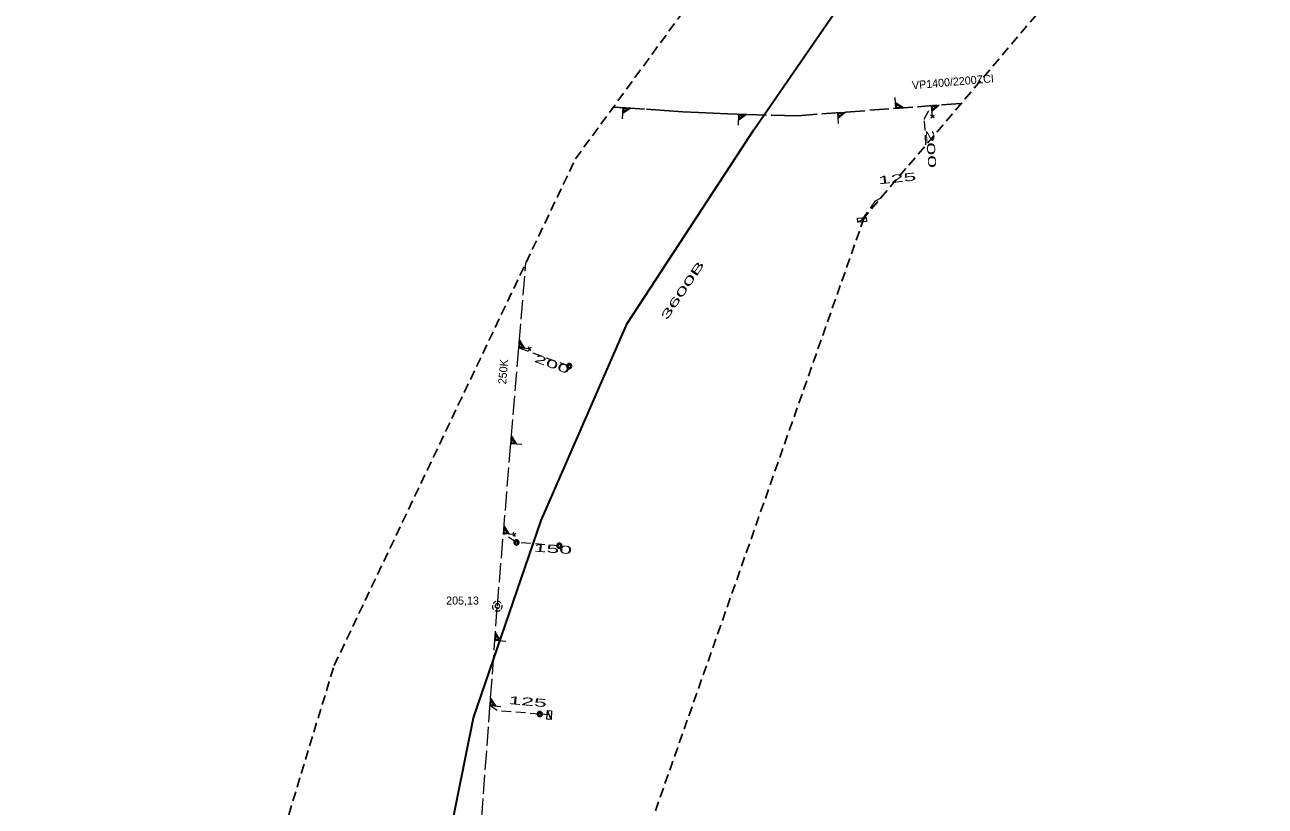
# Model space of a CAD drawing. Extents: x -744446 to -743929, y -1041261 to -1040599.
# Drawn here: x -744445.1 to -744321.1, y -1040836.2 to -1040758 of the extents above; entities that cross this region are included whole.
import ezdxf

# ---------------------------------------------------------------- set-up
doc = ezdxf.new("R2010")
doc.units = 0
doc.header["$LTSCALE"] = 0.32
doc.linetypes.add('LONG_DASHED', pattern=[7.5, 6, -1.5])
doc.linetypes.add('MEDIUM_DASHED', pattern=[4.5, 3, -1.5])
for name, color, linetype, lineweight in [('1', 7, 'MEDIUM_DASHED', 25), ('18', 7, 'Continuous', 13), ('20', 7, 'LONG_DASHED', 13), ('49', 7, 'MEDIUM_DASHED', 13)]:
    doc.layers.add(name, color=color, linetype=linetype, lineweight=lineweight)

msp = doc.modelspace()

# ---------------------------------------------------------------- linework, layer by layer
at = {"layer": '1'}
msp.add_lwpolyline([(-744438.077, -1041259.731), (-744438.679, -1041250.888), (-744445.125, -1041198.426), (-744434.434, -1041080.103), (-744426.87, -1040938.41), (-744425.446, -1040859.072), (-744414.192, -1040822.094), (-744390.076, -1040771.45), (-744357.118, -1040726.434), (-744307.278, -1040693.475), (-744241.36, -1040670.967), (-743937.498, -1040598.618), (-743928.655, -1040619.519), (-744129.684, -1040665.585), (-744218.109, -1040687.29), (-744311.358, -1040718.641), (-744361.198, -1040777.323), (-744391.745, -1040864.141), (-744411.355, -1041059.185), (-744416.379, -1041145.154), (-744432.569, -1041193.163), (-744432.047, -1041202.053), (-744422.803, -1041230.992), (-744424.813, -1041260.936)], close=True, dxfattribs=at)
at = {"layer": '18'}
for p, q in [((-744354.206, -1040767.325), (-744354.56, -1040767.082)), ((-744354.544, -1040767.339), (-744354.192, -1040767.067)), ((-744361.838, -1040777.771), (-744360.989, -1040777.31)), ((-744394.495, -1040790.289), (-744394.79, -1040790.601)), ((-744394.534, -1040790.625), (-744394.747, -1040790.235)), ((-744396.036, -1040808.866), (-744396.331, -1040809.178)), ((-744396.075, -1040809.202), (-744396.288, -1040808.812)), ((-744392.506, -1040827.502), (-744392.859, -1040826.603))]:
    msp.add_line(p, q, dxfattribs=at)
for points in [[(-744358.13, -1040765.299), (-744358.047, -1040766.392), (-744357.279, -1040766.334), (-744358.091, -1040765.815)], [(-744385.356, -1040767.426), (-744385.303, -1040766.331), (-744384.534, -1040766.368), (-744385.331, -1040766.908)], [(-744385.276, -1040766.793), (-744385.256, -1040766.377), (-744384.69, -1040766.404), (-744385.276, -1040766.794)], [(-744385.225, -1040766.711), (-744385.211, -1040766.421), (-744384.839, -1040766.438), (-744385.226, -1040766.711)], [(-744373.762, -1040768.081), (-744373.722, -1040766.986), (-744372.953, -1040767.014), (-744373.743, -1040767.564)], [(-744363.753, -1040767.919), (-744363.836, -1040766.826), (-744363.068, -1040766.768), (-744363.792, -1040767.402)], [(-744363.751, -1040767.281), (-744363.782, -1040766.866), (-744363.218, -1040766.824), (-744363.751, -1040767.282)], [(-744363.711, -1040767.194), (-744363.732, -1040766.903), (-744363.361, -1040766.875), (-744363.712, -1040767.194)], [(-744358.031, -1040765.929), (-744358, -1040766.344), (-744357.436, -1040766.301), (-744358.031, -1040765.928)], [(-744357.978, -1040766.009), (-744357.956, -1040766.3), (-744357.586, -1040766.272), (-744357.979, -1040766.009)], [(-744354.375, -1040767.209), (-744354.458, -1040766.117), (-744353.69, -1040766.059), (-744354.414, -1040766.693)], [(-744354.373, -1040766.571), (-744354.404, -1040766.157), (-744353.84, -1040766.114), (-744354.373, -1040766.573)], [(-744354.333, -1040766.484), (-744354.355, -1040766.193), (-744353.984, -1040766.165), (-744354.334, -1040766.484)], [(-744373.689, -1040767.448), (-744373.674, -1040767.032), (-744373.108, -1040767.052), (-744373.689, -1040767.449)], [(-744373.639, -1040767.365), (-744373.629, -1040767.074), (-744373.257, -1040767.088), (-744373.64, -1040767.365)], [(-744394.636, -1040790.438), (-744395.728, -1040790.347), (-744395.664, -1040789.58), (-744395.152, -1040790.395)], [(-744395.266, -1040790.336), (-744395.68, -1040790.301), (-744395.633, -1040789.737), (-744395.264, -1040790.336)], [(-744395.345, -1040790.282), (-744395.636, -1040790.258), (-744395.605, -1040789.887), (-744395.345, -1040790.283)], [(-744395.43, -1040800.022), (-744396.522, -1040799.931), (-744396.458, -1040799.164), (-744395.946, -1040799.979)], [(-744396.059, -1040799.92), (-744396.474, -1040799.885), (-744396.427, -1040799.321), (-744396.058, -1040799.92)], [(-744396.139, -1040799.866), (-744396.429, -1040799.842), (-744396.398, -1040799.471), (-744396.139, -1040799.867)], [(-744396.177, -1040809.015), (-744397.269, -1040808.924), (-744397.205, -1040808.157), (-744396.693, -1040808.972)], [(-744396.807, -1040808.913), (-744397.221, -1040808.878), (-744397.174, -1040808.314), (-744396.805, -1040808.913)], [(-744396.886, -1040808.859), (-744397.177, -1040808.835), (-744397.146, -1040808.464), (-744396.886, -1040808.86)], [(-744398.368, -1040816.101), (-744398.374, -1040816.178), (-744398.369, -1040816.255), (-744398.352, -1040816.33), (-744398.323, -1040816.401), (-744398.282, -1040816.467), (-744398.267, -1040816.489)], [(-744398.023, -1040815.709), (-744398.094, -1040815.737), (-744398.161, -1040815.776), (-744398.221, -1040815.824), (-744398.272, -1040815.881), (-744398.296, -1040815.915)], [(-744398.11, -1040816.618), (-744398.04, -1040816.649), (-744397.965, -1040816.668), (-744397.889, -1040816.675), (-744397.812, -1040816.67), (-744397.737, -1040816.653), (-744397.665, -1040816.625), (-744397.605, -1040816.59)], [(-744397.482, -1040815.892), (-744397.532, -1040815.834), (-744397.59, -1040815.784), (-744397.655, -1040815.743), (-744397.726, -1040815.714), (-744397.775, -1040815.7)], [(-744397.487, -1040816.478), (-744397.446, -1040816.413), (-744397.415, -1040816.343), (-744397.396, -1040816.268), (-744397.388, -1040816.192), (-744397.393, -1040816.115), (-744397.399, -1040816.08)], [(-744397.031, -1040819.692), (-744398.124, -1040819.611), (-744398.067, -1040818.844), (-744397.548, -1040819.654)], [(-744397.662, -1040819.596), (-744398.076, -1040819.565), (-744398.035, -1040819), (-744397.661, -1040819.596)], [(-744397.742, -1040819.542), (-744398.032, -1040819.521), (-744398.005, -1040819.15), (-744397.742, -1040819.543)], [(-744397.515, -1040826.224), (-744398.608, -1040826.143), (-744398.551, -1040825.376), (-744398.032, -1040826.186)], [(-744398.146, -1040826.128), (-744398.56, -1040826.097), (-744398.519, -1040825.532), (-744398.145, -1040826.128)], [(-744398.226, -1040826.074), (-744398.516, -1040826.053), (-744398.489, -1040825.682), (-744398.226, -1040826.075)]]:
    msp.add_lwpolyline(points, dxfattribs=at)
for points in [[(-744361.865, -1040777.36), (-744360.993, -1040777.31), (-744360.969, -1040777.721), (-744361.842, -1040777.771)], [(-744390.424, -1040792.17), (-744390.429, -1040792.114), (-744390.446, -1040792.061), (-744390.475, -1040792.012), (-744390.514, -1040791.971), (-744390.559, -1040791.939), (-744390.612, -1040791.917), (-744390.667, -1040791.906), (-744390.723, -1040791.908), (-744390.777, -1040791.921), (-744390.828, -1040791.946), (-744390.873, -1040791.981), (-744390.909, -1040792.024), (-744390.934, -1040792.074), (-744390.949, -1040792.129), (-744390.951, -1040792.185), (-744390.943, -1040792.24), (-744390.922, -1040792.293), (-744390.891, -1040792.339), (-744390.85, -1040792.378), (-744390.803, -1040792.408), (-744390.75, -1040792.427), (-744390.694, -1040792.434), (-744390.637, -1040792.43), (-744390.583, -1040792.413), (-744390.534, -1040792.386), (-744390.493, -1040792.348), (-744390.46, -1040792.303), (-744390.436, -1040792.252), (-744390.424, -1040792.197)], [(-744390.483, -1040792.173), (-744390.489, -1040792.124), (-744390.507, -1040792.078), (-744390.534, -1040792.037), (-744390.571, -1040792.004), (-744390.615, -1040791.982), (-744390.664, -1040791.97), (-744390.713, -1040791.97), (-744390.761, -1040791.982), (-744390.804, -1040792.005), (-744390.842, -1040792.038), (-744390.87, -1040792.079), (-744390.887, -1040792.126), (-744390.892, -1040792.175), (-744390.886, -1040792.224), (-744390.868, -1040792.27), (-744390.84, -1040792.31), (-744390.803, -1040792.343), (-744390.759, -1040792.365), (-744390.71, -1040792.377), (-744390.661, -1040792.376), (-744390.613, -1040792.364), (-744390.57, -1040792.34), (-744390.532, -1040792.307), (-744390.505, -1040792.266), (-744390.489, -1040792.219)], [(-744390.542, -1040792.177), (-744390.548, -1040792.135), (-744390.565, -1040792.097), (-744390.593, -1040792.066), (-744390.627, -1040792.043), (-744390.668, -1040792.032), (-744390.71, -1040792.032), (-744390.75, -1040792.044), (-744390.784, -1040792.067), (-744390.811, -1040792.099), (-744390.828, -1040792.137), (-744390.833, -1040792.178), (-744390.828, -1040792.22), (-744390.809, -1040792.257), (-744390.782, -1040792.289), (-744390.745, -1040792.311), (-744390.706, -1040792.322), (-744390.664, -1040792.321), (-744390.624, -1040792.308), (-744390.59, -1040792.285), (-744390.563, -1040792.252), (-744390.547, -1040792.214)], [(-744395.697, -1040809.799), (-744395.703, -1040809.743), (-744395.72, -1040809.69), (-744395.749, -1040809.641), (-744395.787, -1040809.6), (-744395.833, -1040809.568), (-744395.885, -1040809.546), (-744395.94, -1040809.535), (-744395.996, -1040809.537), (-744396.051, -1040809.55), (-744396.102, -1040809.575), (-744396.146, -1040809.61), (-744396.182, -1040809.653), (-744396.207, -1040809.703), (-744396.222, -1040809.758), (-744396.225, -1040809.814), (-744396.216, -1040809.869), (-744396.195, -1040809.922), (-744396.164, -1040809.968), (-744396.124, -1040810.007), (-744396.076, -1040810.037), (-744396.023, -1040810.056), (-744395.967, -1040810.063), (-744395.911, -1040810.059), (-744395.857, -1040810.042), (-744395.808, -1040810.015), (-744395.766, -1040809.977), (-744395.733, -1040809.932), (-744395.71, -1040809.881), (-744395.698, -1040809.826)], [(-744395.756, -1040809.802), (-744395.762, -1040809.753), (-744395.78, -1040809.707), (-744395.808, -1040809.666), (-744395.845, -1040809.633), (-744395.889, -1040809.611), (-744395.937, -1040809.599), (-744395.986, -1040809.599), (-744396.034, -1040809.611), (-744396.078, -1040809.634), (-744396.115, -1040809.667), (-744396.143, -1040809.708), (-744396.16, -1040809.755), (-744396.166, -1040809.804), (-744396.159, -1040809.853), (-744396.141, -1040809.899), (-744396.113, -1040809.939), (-744396.076, -1040809.972), (-744396.032, -1040809.994), (-744395.983, -1040810.006), (-744395.934, -1040810.005), (-744395.886, -1040809.993), (-744395.843, -1040809.969), (-744395.806, -1040809.936), (-744395.778, -1040809.895), (-744395.762, -1040809.848)], [(-744395.815, -1040809.806), (-744395.821, -1040809.764), (-744395.838, -1040809.726), (-744395.866, -1040809.695), (-744395.901, -1040809.672), (-744395.941, -1040809.661), (-744395.983, -1040809.661), (-744396.023, -1040809.673), (-744396.058, -1040809.696), (-744396.085, -1040809.728), (-744396.102, -1040809.766), (-744396.107, -1040809.807), (-744396.101, -1040809.849), (-744396.083, -1040809.886), (-744396.055, -1040809.918), (-744396.019, -1040809.94), (-744395.979, -1040809.951), (-744395.937, -1040809.95), (-744395.897, -1040809.937), (-744395.863, -1040809.914), (-744395.836, -1040809.881), (-744395.82, -1040809.843)], [(-744391.414, -1040810.126), (-744391.419, -1040810.07), (-744391.436, -1040810.017), (-744391.465, -1040809.968), (-744391.504, -1040809.927), (-744391.549, -1040809.895), (-744391.602, -1040809.873), (-744391.657, -1040809.862), (-744391.713, -1040809.864), (-744391.767, -1040809.877), (-744391.818, -1040809.902), (-744391.863, -1040809.937), (-744391.899, -1040809.98), (-744391.924, -1040810.03), (-744391.939, -1040810.085), (-744391.941, -1040810.141), (-744391.933, -1040810.196), (-744391.912, -1040810.249), (-744391.88, -1040810.295), (-744391.84, -1040810.334), (-744391.793, -1040810.364), (-744391.74, -1040810.383), (-744391.684, -1040810.39), (-744391.627, -1040810.386), (-744391.573, -1040810.369), (-744391.524, -1040810.342), (-744391.483, -1040810.304), (-744391.45, -1040810.259), (-744391.426, -1040810.208), (-744391.414, -1040810.153)], [(-744391.473, -1040810.129), (-744391.478, -1040810.08), (-744391.497, -1040810.034), (-744391.524, -1040809.993), (-744391.561, -1040809.96), (-744391.605, -1040809.938), (-744391.654, -1040809.926), (-744391.703, -1040809.926), (-744391.75, -1040809.938), (-744391.794, -1040809.961), (-744391.831, -1040809.994), (-744391.86, -1040810.035), (-744391.877, -1040810.082), (-744391.882, -1040810.131), (-744391.875, -1040810.18), (-744391.858, -1040810.226), (-744391.83, -1040810.266), (-744391.793, -1040810.299), (-744391.749, -1040810.321), (-744391.7, -1040810.333), (-744391.651, -1040810.332), (-744391.603, -1040810.32), (-744391.559, -1040810.296), (-744391.522, -1040810.263), (-744391.495, -1040810.222), (-744391.478, -1040810.175)], [(-744391.532, -1040810.133), (-744391.538, -1040810.091), (-744391.554, -1040810.053), (-744391.583, -1040810.022), (-744391.617, -1040809.999), (-744391.657, -1040809.988), (-744391.7, -1040809.988), (-744391.74, -1040810), (-744391.774, -1040810.023), (-744391.801, -1040810.055), (-744391.818, -1040810.093), (-744391.823, -1040810.134), (-744391.818, -1040810.176), (-744391.799, -1040810.213), (-744391.772, -1040810.245), (-744391.735, -1040810.267), (-744391.696, -1040810.278), (-744391.654, -1040810.277), (-744391.614, -1040810.264), (-744391.58, -1040810.241), (-744391.553, -1040810.208), (-744391.537, -1040810.17)], [(-744397.639, -1040816.161), (-744397.645, -1040816.109), (-744397.663, -1040816.059), (-744397.691, -1040816.015), (-744397.729, -1040815.978), (-744397.774, -1040815.951), (-744397.824, -1040815.935), (-744397.876, -1040815.93), (-744397.928, -1040815.937), (-744397.977, -1040815.956), (-744398.021, -1040815.986), (-744398.056, -1040816.025), (-744398.082, -1040816.07), (-744398.097, -1040816.121), (-744398.1, -1040816.173), (-744398.092, -1040816.225), (-744398.071, -1040816.273), (-744398.041, -1040816.316), (-744398.001, -1040816.351), (-744397.955, -1040816.375), (-744397.904, -1040816.389), (-744397.852, -1040816.391), (-744397.8, -1040816.381), (-744397.752, -1040816.359), (-744397.71, -1040816.327), (-744397.677, -1040816.287), (-744397.653, -1040816.24), (-744397.641, -1040816.189)], [(-744393.364, -1040826.958), (-744393.37, -1040826.902), (-744393.387, -1040826.849), (-744393.416, -1040826.8), (-744393.454, -1040826.759), (-744393.5, -1040826.727), (-744393.552, -1040826.705), (-744393.607, -1040826.694), (-744393.663, -1040826.696), (-744393.718, -1040826.709), (-744393.769, -1040826.734), (-744393.813, -1040826.769), (-744393.849, -1040826.812), (-744393.874, -1040826.862), (-744393.889, -1040826.917), (-744393.892, -1040826.973), (-744393.883, -1040827.028), (-744393.862, -1040827.081), (-744393.831, -1040827.127), (-744393.791, -1040827.166), (-744393.743, -1040827.196), (-744393.69, -1040827.215), (-744393.634, -1040827.222), (-744393.578, -1040827.218), (-744393.524, -1040827.201), (-744393.475, -1040827.174), (-744393.433, -1040827.136), (-744393.4, -1040827.091), (-744393.377, -1040827.04), (-744393.365, -1040826.985)], [(-744393.423, -1040826.961), (-744393.429, -1040826.912), (-744393.447, -1040826.866), (-744393.475, -1040826.825), (-744393.512, -1040826.792), (-744393.556, -1040826.77), (-744393.604, -1040826.758), (-744393.653, -1040826.758), (-744393.701, -1040826.77), (-744393.745, -1040826.793), (-744393.782, -1040826.826), (-744393.81, -1040826.867), (-744393.827, -1040826.914), (-744393.833, -1040826.963), (-744393.826, -1040827.012), (-744393.808, -1040827.058), (-744393.78, -1040827.098), (-744393.743, -1040827.131), (-744393.699, -1040827.153), (-744393.65, -1040827.165), (-744393.601, -1040827.164), (-744393.553, -1040827.152), (-744393.51, -1040827.128), (-744393.473, -1040827.095), (-744393.445, -1040827.054), (-744393.429, -1040827.007)], [(-744393.482, -1040826.965), (-744393.488, -1040826.923), (-744393.505, -1040826.885), (-744393.533, -1040826.854), (-744393.568, -1040826.831), (-744393.608, -1040826.82), (-744393.65, -1040826.82), (-744393.69, -1040826.832), (-744393.725, -1040826.855), (-744393.752, -1040826.887), (-744393.769, -1040826.925), (-744393.774, -1040826.966), (-744393.768, -1040827.008), (-744393.75, -1040827.045), (-744393.722, -1040827.077), (-744393.686, -1040827.099), (-744393.646, -1040827.11), (-744393.604, -1040827.109), (-744393.564, -1040827.096), (-744393.53, -1040827.073), (-744393.503, -1040827.04), (-744393.487, -1040827.002)], [(-744392.917, -1040827.479), (-744392.859, -1040826.607), (-744392.448, -1040826.634), (-744392.506, -1040827.506)]]:
    msp.add_lwpolyline(points, close=True, dxfattribs=at)
at = {"layer": '20'}
msp.add_line((-744397.87, -1040816.172), (-744395.019, -1040781.831), dxfattribs=at)
at = {"layer": '20', "linetype": 'Continuous', "lineweight": 35}
msp.add_lwpolyline([(-744429.62, -1041252.21), (-744428.789, -1041237.94), (-744437.959, -1041195.193), (-744423.3, -1041145.69), (-744417.879, -1041053.98), (-744409.949, -1040917.67), (-744407.76, -1040880.01), (-744407.219, -1040869.23), (-744404.395, -1040847.829), (-744400.25, -1040827.35), (-744393.491, -1040807.621), (-744384.879, -1040787.9), (-744372.238, -1040768.547), (-744361.26, -1040752.62), (-744345.317, -1040736.555), (-744330.739, -1040723.14), (-744312.333, -1040710.859), (-744294.67, -1040700.75), (-744274.728, -1040692.583), (-744254.699, -1040686.49), (-744133.87, -1040657.39), (-743953.289, -1040613.85), (-743946.017, -1040612.141)], dxfattribs=at)
at = {"layer": '20', "lineweight": 25}
msp.add_lwpolyline([(-744386.294, -1040766.285), (-744385.072, -1040766.343), (-744382.968, -1040766.48), (-744381.149, -1040766.608), (-744379.342, -1040766.722), (-744377.721, -1040766.813), (-744376.283, -1040766.884), (-744374.846, -1040766.947), (-744372.878, -1040767.018), (-744370.431, -1040767.084), (-744369.153, -1040767.109), (-744367.82, -1040767.128), (-744351.492, -1040765.895)], dxfattribs=at)
at = {"layer": '20'}
msp.add_lwpolyline([(-744401.298, -1040867.055), (-744399.614, -1040839.73), (-744397.87, -1040816.172)], dxfattribs=at)
at = {"layer": '49'}
for p, q in [((-744390.688, -1040792.183), (-744395.727, -1040790.353)), ((-744392.687, -1040827.048), (-744393.628, -1040826.971))]:
    msp.add_line(p, q, dxfattribs=at)
for points in [[(-744355.014, -1040770.042), (-744355.186, -1040767.455), (-744354.463, -1040766.119)], [(-744361.409, -1040777.536), (-744360.048, -1040775.652), (-744359.499, -1040775.323)], [(-744391.678, -1040810.139), (-744395.961, -1040809.812), (-744397.268, -1040808.93)], [(-744393.628, -1040826.971), (-744397.903, -1040826.621), (-744398.608, -1040826.144)]]:
    msp.add_lwpolyline(points, dxfattribs=at)

# ---------------------------------------------------------------- texts
at = {"layer": '1'}
for s, rotation, p in [('VP1400/2200ZCI', 5, (-744356.377, -1040764.489)), ('250K', 85, (-744397.006, -1040794.01))]:
    msp.add_text(s, height=0.8, rotation=rotation, dxfattribs=at).set_placement(p)
for s, rotation, width, p in [('200 ', 274, 2.15, (-744355.035, -1040768.552)), ('125 ', 6, 2.15, (-744359.773, -1040773.99)), ('3600B ', 56, 2.2, (-744380.93, -1040787.63)), ('200 ', 340, 2.05, (-744394.258, -1040791.712)), ('150 ', 356, 2.15, (-744394.266, -1040810.706)), ('125 ', 355, 2.15, (-744396.79, -1040825.948))]:
    msp.add_text(s, height=0.8, rotation=rotation, dxfattribs=dict(at, width=width)).set_placement(p)
msp.add_text('205,13', height=0.8, dxfattribs=at).set_placement((-744402.992, -1040816.012))

doc.saveas('drawing.dxf')
